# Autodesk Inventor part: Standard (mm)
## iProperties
Shininess: 64.0
Length Units: 11269
Angle Units: 11279
Time Units: 11290
Mass Units: 11283
Length Display Precision: 3
Angle Display Precision: 2
Compacted: True
Part Number: Standard (mm)
Document SubType Name: Modeling
Created: 2002-07
Density: 0.0
Volumn: 0.0
Area: 0.0
PropertySet Name: Model Information
Control State: 0
Master: False
Checked Out: False
